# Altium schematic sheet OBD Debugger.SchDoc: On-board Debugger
size A3; CompanyName: Hitex GmbH; Address1: Greschbachstr. 12; Address2: 76229 Karlsruhe, Germany; Address3: www.hitex.com; DocumentNumber: 5; SheetNumber: 5; SheetTotal: 8; PageSetup: Record=PageOptions¦CenterHorizontal=True¦CenterVertical=True¦PrintScale=1.04¦XCorrection=1.00¦YCorrection=1.00¦PrintKind=0¦BorderSize=5000000¦LeftOffset=0¦BottomOffset=0¦Orientation=2¦PaperLength=1000¦PaperWidth=1000¦Scale=100¦PaperSource=7¦PrintQuality=1200¦MediaType=1¦DitherType=10¦PaperKind=A3¦PrintScaleMode=1
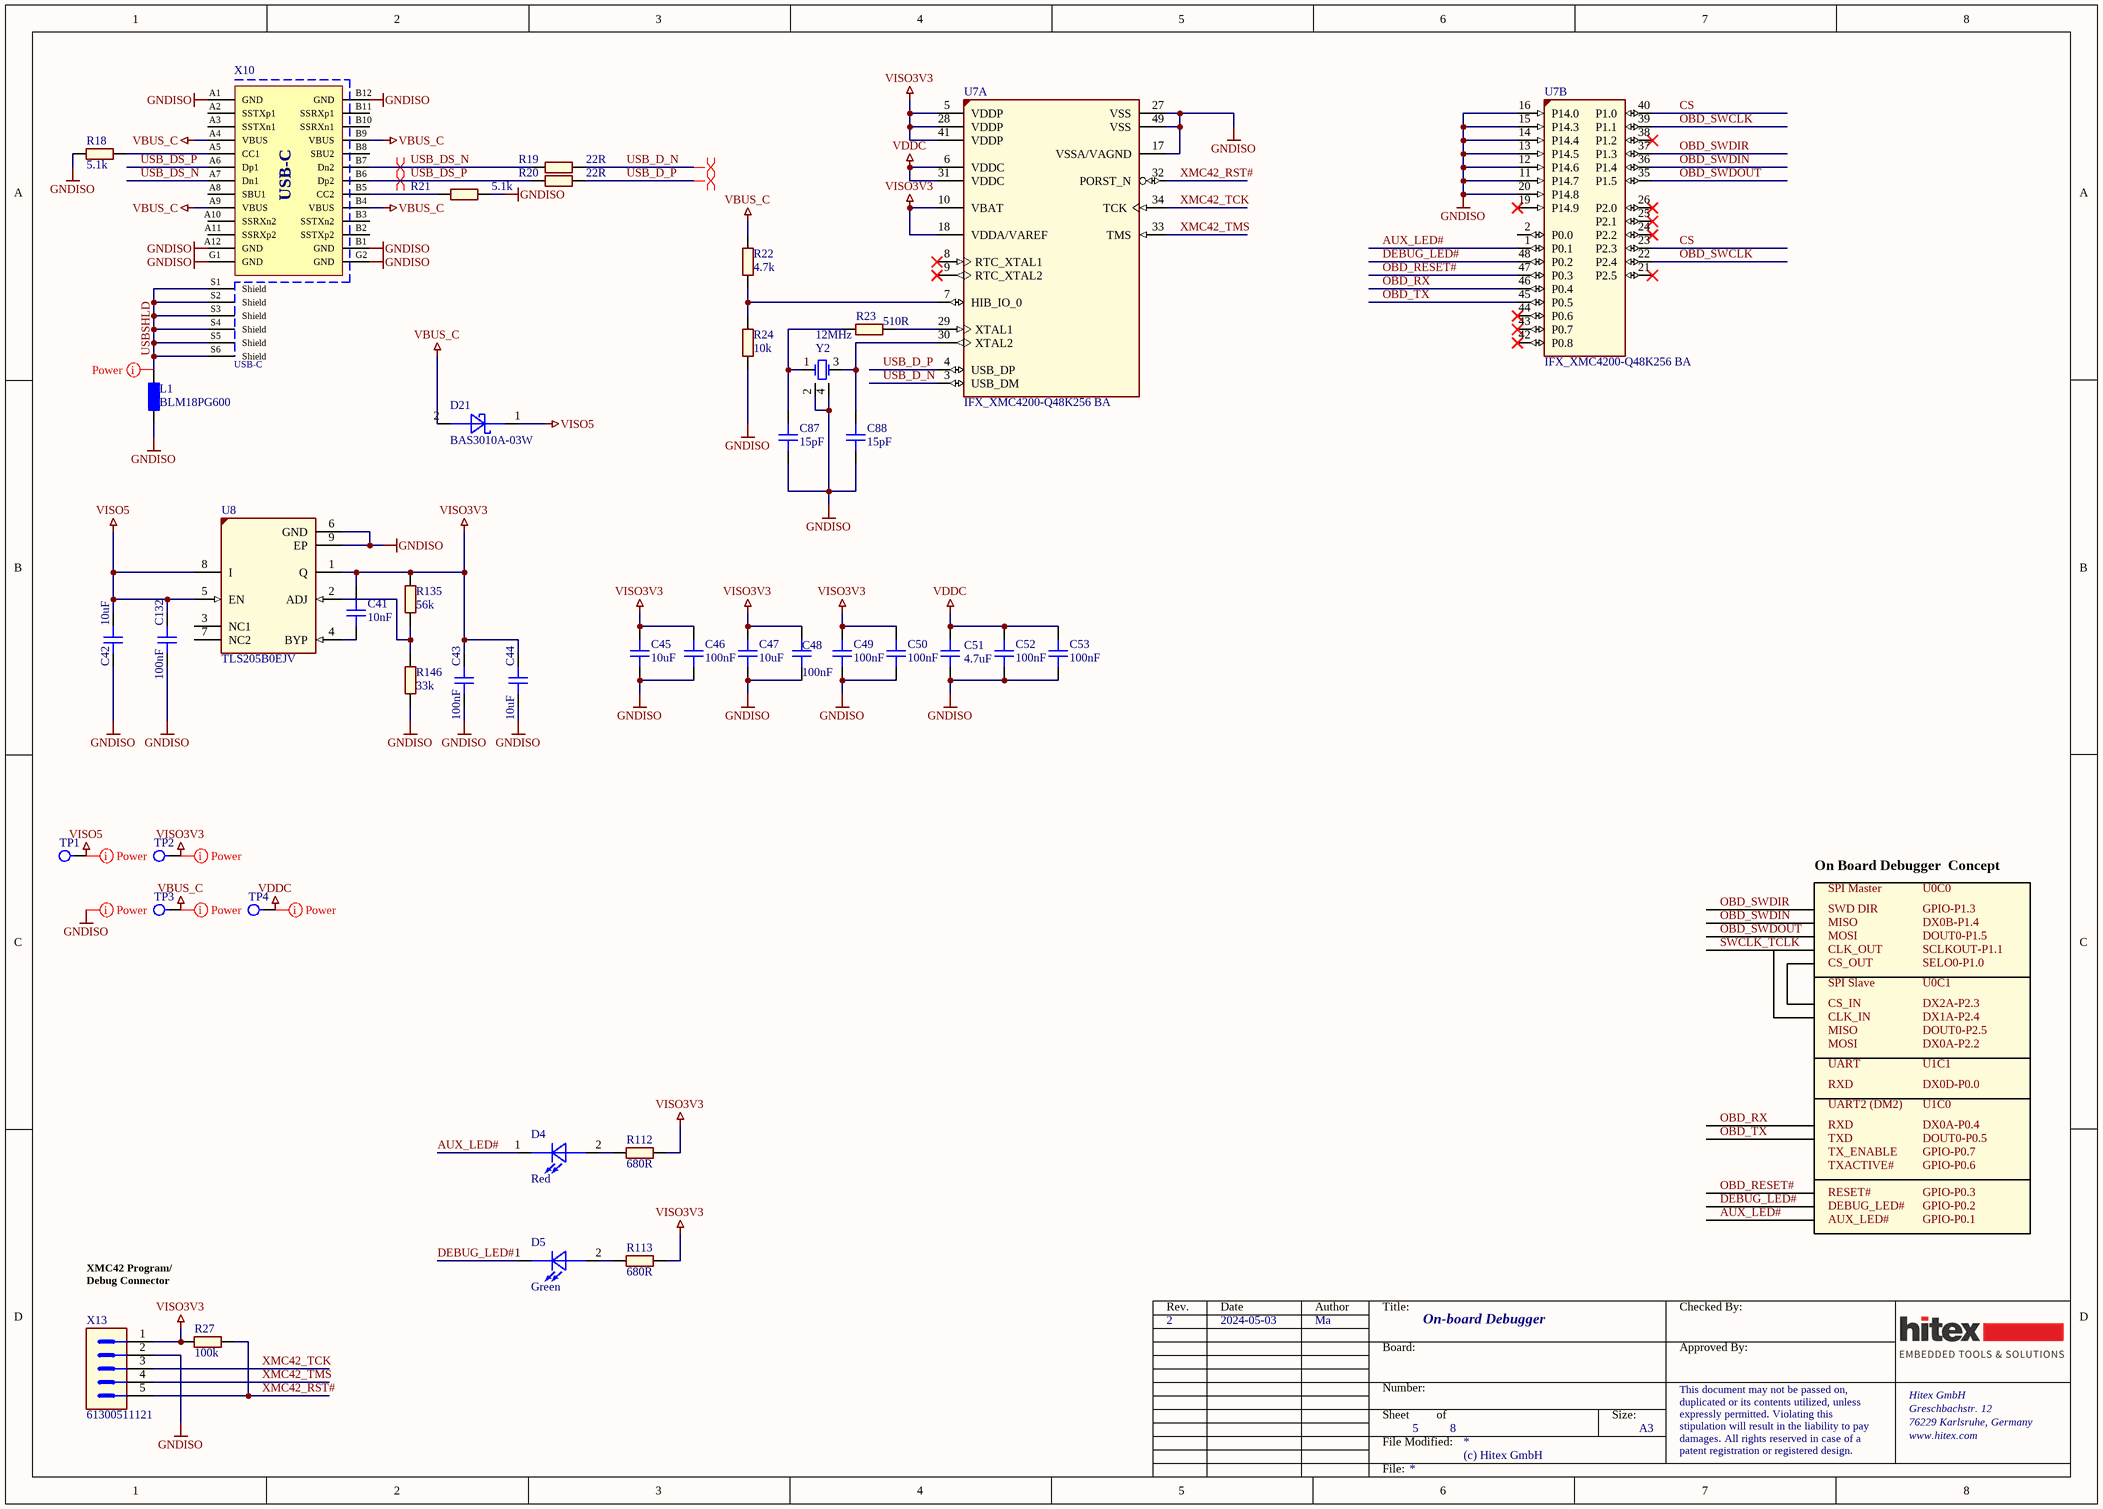
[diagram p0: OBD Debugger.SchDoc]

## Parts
C41  10nF  [CAPC1005X55N-0]
C42  10uF  [CAPC3216X180N]
C43  100nF  [CAPC1005X60N]
C44  10uF  [CAPC3216X180N]
C45  10uF  [CAPC3216X180N]
C46  100nF  [CAPC1005X55N-0]
C47  10uF  [CAPC3216X180N]
C48  100nF  [CAPC1005X55N-0]
C49  100nF  [CAPC1005X55N-0]
C50  100nF  [CAPC1005X55N-0]
C51  4.7uF  [CAPC2013X145N-3]
C52  100nF  [CAPC1005X55N-0]
C53  100nF  [CAPC1005X55N-0]
C87  15pF  [CAPC1005X55N-0]
C88  15pF  [CAPC1005X55N-0]
C132  100nF  [CAPC1005X60N]
D4  Red  [LEDSC160X80X80-2N]
D5  Green  [LEDSC160X80X40-2N]
D21  BAS3010A-03W  [SOD2513X110N]
L1  BLM18PG600  [INDC1608N]
R18  5.1k  [RESC1609X50N]
R19  22R  [RESC1005X40N]
R20  22R  [RESC1005X40N]
R21  5.1k  [RESC1609X50N]
R22  4.7k  [RESC1005X40N-1]
R23  510R  [RESC1005X40N]
R24  10k  [RESC1005X40N]
R27  100k  [RESC1005X40N]
R112  680R  [RESC1608X55N-1]
R113  680R  [RESC1608X55N-1]
R135  56k  [RESC1005X40N]
R146  33k  [RESC1005X40N]
TP1  (no value)  [TP_RD_SMD_1MM]  (no BOM)
TP2  (no value)  [TP_RD_SMD_1MM]  (no BOM)
TP3  (no value)  [TP_RD_SMD_1MM]  (no BOM)
TP4  (no value)  [TP_RD_SMD_1MM]  (no BOM)
U7  IFX_XMC4200-Q48K256 BA  [QFN50P700X700X90-49N-8]  (parts A,B of 2)
U8  TLS205B0EJV  [SOIC127P600X170-9N-3-V1]
X10  USB-C  [632723300011]
X13  61300511121  [CON-M-THT-61300511121]
Y2  12MHz  [Oscillator_3225]

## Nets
GNDISO: C42.1 C43.1 C44.1 C45.1 C46.1 C47.1 C48.1 C49.1 C50.1 C51.1 C52.1 C53.1 C87.1 C88.1 C132.1 L1.1 R18.1 R21.2 R24.1 R146.1 U7.11(P14.7) U7.12(P14.6) U7.13(P14.5) U7.14(P14.4) U7.15(P14.3) U7.16(P14.0) U7.17(VSSA/VAGND) U7.20(P14.8) U7.27(VSS) U7.49(VSS) U8.6(GND) U8.9(EP) X10.A1(GND) X10.A12(GND) X10.B1(GND) X10.B12(GND) X10.G1(GND) X10.G2(GND) X13.2 Y2.2(GND) Y2.4(GND)
VBUS_C: D21.2(Anode) R22.2 TP3.1 X10.A4(VBUS) X10.A9(VBUS) X10.B4(VBUS) X10.B9(VBUS)
VDDC: C51.2 C52.2 C53.2 TP4.1 U7.6(VDDC) U7.31(VDDC)
VISO3V3: C41.2 C43.2 C44.2 C45.2 C46.2 C47.2 C48.2 C49.2 C50.2 R27.2 R112.1 R113.2 R135.2 TP2.1 U7.5(VDDP) U7.10(VBAT) U7.18(VDDA/VAREF) U7.28(VDDP) U7.41(VDDP) U8.1(Q) X13.1
VISO5: C42.2 C132.2 D21.1(Cathode) TP1.1 U8.5(EN) U8.8(I)
AUX_LED#: D4.1(Cathode) U7.1(P0.1)
CS: U7.23(P2.3) U7.40(P1.0)
DEBUG_LED#: D5.1(Cathode) U7.48(P0.2)
OBD_RESET#: U7.47(P0.3)
OBD_RX: U7.46(P0.4)
OBD_SWCLK: U7.22(P2.4) U7.39(P1.1)
OBD_SWDIN: U7.36(P1.4)
OBD_SWDIR: U7.37(P1.3)
OBD_SWDOUT: U7.35(P1.5)
OBD_TX: U7.45(P0.5)
USB_D_N: R19.2 U7.3(USB_DM)
USB_D_P: R20.2 U7.4(USB_DP)
USB_DS_N: R19.1 X10.A7(Dn1) X10.B7(Dn2)
USB_DS_P: R20.1 X10.A6(Dp1) X10.B6(Dp2)
USBSHLD: L1.2 X10.S1(Shield) X10.S2(Shield) X10.S3(Shield) X10.S4(Shield) X10.S5(Shield) X10.S6(Shield)
XMC42_RST#: R27.1 U7.32(PORST_N) X13.5
XMC42_TCK: U7.34(TCK) X13.3
XMC42_TMS: U7.33(TMS) X13.4
NetC41_1: C41.1 U8.4(BYP)
NetC87_2: C87.2 R23.1 Y2.1(OSC1)
NetC88_2: C88.2 U7.30(XTAL2) Y2.3(OSC2)
NetD4_2: D4.2(Anode) R112.2
NetD5_2: D5.2(Anode) R113.1
NetR18_2: R18.2 X10.A5(CC1)
NetR21_1: R21.1 X10.B5(CC2)
NetR22_1: R22.1 R24.2 U7.7(HIB_IO_0)
NetR23_2: R23.2 U7.29(XTAL1)
NetR135_1: R135.1 R146.2 U8.2(ADJ)

Not connected (* = marked no-connect by the designer): U7 2(P0.0) 8(RTC_XTAL1)* 9(RTC_XTAL2)* 19(P14.9)* 21(P2.5)* 24(P2.2)* 25(P2.1)* 26(P2.0)* 38(P1.2)* 42(P0.8)* 43(P0.7)* 44(P0.6)*; U8 3(NC1) 7(NC2); X10 A2(SSTXp1) A3(SSTXn1) A8(SBU1) A10(SSRXn2) A11(SSRXp2) B2(SSTXp2) B3(SSTXn2) B8(SBU2) B10(SSRXn1) B11(SSRXp1)

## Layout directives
differential pair; differential pair class DIFF90R: USB_D_N, USB_D_P, USB_DS_N, USB_DS_P
net class Power: GNDISO, USBSHLD, VBUS_C, VDDC, VISO3V3, VISO5

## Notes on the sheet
- OBD_SWDIN
- OBD_SWDIR
- On Board Debugger  Concept
- SPI Master
- SWD DIR
- U0C0
- GPIO-P1.3
- SWCLK_TCLK
- OBD_SWDOUT
- SPI Slave
- MOSI
- CLK_OUT
- MISO
- CS_OUT
- SCLKOUT-P1.1
- DX0B-P1.4
- U0C1
- DOUT0-P1.5
- SELO0-P1.0
- CS_IN
- CLK_IN
- DX2A-P2.3
- DX1A-P2.4
- DOUT0-P2.5
- DX0A-P2.2
- OBD_RX
- UART2 (DM2)
- RXD
- UART
- DX0A-P0.4
- U1C0
- DX0D-P0.0
- U1C1
- OBD_TX
- OBD_RESET#
- TXD
- TXACTIVE#
- TX_ENABLE
- DOUT0-P0.5
- GPIO-P0.6
- GPIO-P0.7
- DEBUG_LED#
- AUX_LED#
- RESET#
- GPIO-P0.3
- GPIO-P0.2
- GPIO-P0.1
- XMC42 Program/
  Debug Connector
- 2
- 2024-05-03
- Ma
- Labels drawn without touching a wire or pin: GNDISO

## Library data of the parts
C41 = 264563: CAP / CERA / 10nF / 16V / 5% / X7R (EIA) / -55°C to 125°C / 0402(1005) / SMD / -; Multiple Parts: No; Legacy PartNumber: CAP01001706; Manufacturer: MuRata; Manufacturer Order Number: GRM155R71C103JA01; Symbol Type: Capacitor; Single; Standard; 2 Pins; Alternate View: Yes; Article Number: 264563; Version Number: V01; Combined Parameters: TC:X7R (EIA);Tol.:-5%/+5%;Vdc:16V; QuickPick: 10nF / 16V / 5% / X7R (EIA) / 0402 (1005); Type: Standard; Style: Single; Package Metric: 1005; Package Imperial: 0402; ComponentStatus: Released; PLMStatus: Not Recommended For New Designs; HTX: 01.22.0592.0
C42 C44 C45 C47 = 282249: CAP / CERA / 10uF / 50V / 20% / X5R (EIA) / -55°C to 85°C / 1206(3216) / SMD / -; Multiple Parts: No; Manufacturer: MuRata; Manufacturer Order Number: GRM31CR61H106MA12L; Symbol Type: Capacitor; Single; Standard; 2 Pins; Alternate View: Yes; Article Number: 282249; Version Number: V01; Combined Parameters: TC:X5R (EIA);Tol.:-20%/+20%;Vdc:50V; QuickPick: 10uF / 50V / 20% / X5R (EIA) / 1206 (3216); Type: Standard; Style: Single; Package Metric: 3216; Package Imperial: 1206; ComponentStatus: Released; PLMStatus: Not Recommended For New Designs; HTX: 01.22.0647.0
C43 C132 = 507459: CAP / CERA / 100nF / 50V / 10% / X7R (EIA) / -55°C to 125°C / 0402(1005) / SMD / -; Multiple Parts: No; Manufacturer: TDK Corporation; Manufacturer Order Number: C1005X7R1H104K050BE; Symbol Type: Capacitor; Single; Standard; 2 Pins; Alternate View: Yes; Article Number: 507459; Version Number: V01; Combined Parameters: TC:X7R (EIA);Tol.:-10%/+10%;Vdc:50V; QuickPick: 100nF / 50V / 10% / X7R (EIA) / 0402 (1005); Type: Standard; Style: Single; Package Metric: 1005; Package Imperial: 0402; ComponentStatus: Released; PLMStatus: Active; HTX: 01.22.0596.0
C46 C48-C50 C52 C53 = 310625: CAP / CERA / 100nF / 50V / 10% / X7R (EIA) / -55°C to 125°C / 0402(1005) / SMD / -; Multiple Parts: No; Legacy PartNumber: CAP01010920; Manufacturer: MuRata; Manufacturer Order Number: GRM155R71H104KE14D; Symbol Type: Capacitor; Single; Standard; 2 Pins; Alternate View: Yes; Article Number: 310625; Version Number: V01; Combined Parameters: TC:X7R (EIA);Tol.:-10%/+10%;Vdc:50V; QuickPick: 100nF / 50V / 10% / X7R (EIA) / 0402 (1005M); Type: Standard; Style: Single; Package Metric: 1005; Package Imperial: 0402; ComponentStatus: Released; PLMStatus: Active; HTX: 01.22.0596.0
C51 = 673682: CAP / CERA / 4.7uF / 25V / 20% / X7R (EIA) / -55°C to 125°C / 0805 / SMD / -; Multiple Parts: No; Manufacturer: Yageo; Manufacturer Order Number: CC0805MKX7R8BB475; Symbol Type: Capacitor; Single; Standard; 2 Pins; Alternate View: Yes; Article Number: 673682; Version Number: V00; Combined Parameters: TC:X7R (EIA);Tol.:-20%/+20%;Vdc:25V; QuickPick: 4.7uF / 25V / 20% / X7R (EIA) / 0805; Type: Standard; Style: Single; ComponentStatus: Released; PLMStatus: Active; HTX: 01.22.0436.0
C87 C88 = 287311: CAP / CERA / 15pF / 50V / 2% / C0G (EIA) / NP0 / -55°C to 125°C / 0402(1005) / SMD / -; Multiple Parts: No; Legacy PartNumber: CAP01006535; Manufacturer: MuRata; Manufacturer Order Number: GCM1555C1H150GA16; Symbol Type: Capacitor; Single; Standard; 2 Pins; Alternate View: Yes; Article Number: 287311; Version Number: V01; Combined Parameters: TC:C0G (EIA) / NP0;Tol.:-2%/+2%;Vdc:50V; QuickPick: 15pF / 50V / 2% / C0G (EIA) / NP0 / 0402 (1005); Type: Standard; Style: Single; Automotive Qualified: AEC Q200; Package Metric: 1005; Package Imperial: 0402; ComponentStatus: Released; PLMStatus: Active; HTX: 01.22.0669.0
D4 = 494911: ChipLED 0603, Red, 633nm, Temp Raneg(-30 to 85°C); Manufacturer: OSRAM Opto Semiconductors; Manufacturer Order Number: LSQ971-Z; Symbol Type: Standard LED Symbol, 1 Cathode, 2 Anode; Article Number: 494911; Version Number: V01; Combined Parameters: Vf:2.5V;If:25mA;Ur:12V;Ir:10uA;Pmax:-; QuickPick: LED / 603; Type: LED; Style: Single; Automotive Qualified: No; ComponentStatus: Released; PLMStatus: Active; Second Source allowed: Yes; Voltage DC (max): na; HTX: 00.96.0114.0
D5 = 678273: Chip LED, 573nm, Green, Electronic Equipment Applications; Manufacturer: OSRAM Opto Semiconductors; Manufacturer Order Number: LG Q396-PS-35; Symbol Type: Standard LED Symbol, 1 Cathode, 2 Anode; Article Number: 678273; Version Number: V00; Combined Parameters: Vf:2.4V;If:30mA;Ur:12V;Ir:10uA;Pmax:-; QuickPick: LED / 0603; Style: Single; Automotive Qualified: No; ComponentStatus: Released; PLMStatus: Active; Second Source allowed: Yes; Voltage DC (max): na; HTX: 00.96.0122.0
D21 = 420617: Medium Power AF Schottky Diode; Legacy PartNumber: IFX01400145; Manufacturer: Infineon Technologies; Symbol Type: Standard Schottky Diode Symbol, 1 Cathode, 2 Anode; Article Number: 420617; Version Number: V01; Combined Parameters: Vf:410mV;If:1A;Ur:30V;Ir:200uA;Pmax:-; QuickPick: Schottky Diode / SOD323; Style: Single; Automotive Qualified: AEC Q101; ComponentStatus: Released; PLMStatus: Active; Second Source allowed: Yes; Voltage DC (max): na; HTX: 01.41.0047.0
L1 = BLM18PG600SN1D: FERRITE, SMD, 60 OHM, 0603; PartNumber: 01.30.0224.0; Manufacturer: Murata; Designer: Ma; CheckOrientation: false
R18 R21 = 346002: RES / STD / 5.1k / 100mW / 1% / 100ppm/K / -55°C to 155°C / 0603(1608) / SMD / -; Multiple Parts: No; Legacy PartNumber: RES01801223; Manufacturer: Vishay; Manufacturer Order Number: CRCW06035K10FK; Symbol Type: Resistor; Single; Standard; 2 Pins; Alternate View: Yes; Article Number: 346002; Version Number: V01; Combined Parameters: TCR:100ppm/K;Tol.:-1%/+1%;Vdc:75V;Idc:-;P:100mW; QuickPick: 5.1k / 1% / 0.1 / 0603 (1608); Style: Single; Automotive Qualified: AEC Q200; Package Metric: 1608; Package Imperial: 0603; ComponentStatus: Released; PLMStatus: Active; Voltage DC (max): 75V; HTX: 01.02.0481.0
R19 R20 = 340637: RES / STD / 22R / 63mW / 1% / 100ppm/K / -55°C to 155°C / 0402 / SMD / -; Multiple Parts: No; Legacy PartNumber: RES01800151; Manufacturer: Vishay; Manufacturer Order Number: CRCW040222R0FK; Symbol Type: Resistor; Single; Standard; 2 Pins; Alternate View: Yes; Article Number: 340637; Version Number: V01; Combined Parameters: TCR:100ppm/K;Tol.:-1%/+1%;Vdc:50V;Idc:-;P:63mW; QuickPick: 22R / 1% / 0.063 / 0402; Style: Single; Automotive Qualified: AEC Q200; ComponentStatus: Released; PLMStatus: Active; Voltage DC (max): 50V; HTX: 01.02.0779.0
R22 = 327541: RES / STD / 4.7k / 63mW / 1% / 100ppm/K / -55°C to 155°C / 0402(1005) / SMD / -; Multiple Parts: No; Manufacturer: Yageo; Manufacturer Order Number: RC0402FR-074K7L; Symbol Type: Resistor; Single; Standard; 2 Pins; Alternate View: Yes; Article Number: 327541; Version Number: V01; Combined Parameters: TCR:100ppm/K;Tol.:-1%/+1%;Vdc:50V;Idc:-;P:63mW; QuickPick: 4.7k / 1% / 0.063 / 0402 (1005); Style: Single; Package Metric: 1005; Package Imperial: 0402; ComponentStatus: Released; PLMStatus: Active; Voltage DC (max): 50V; HTX: 01.02.0737.0
R23 = 341427: RES / STD / 510R / 63mW / 1% / 100ppm/K / -55°C to 155°C / 0402(1005) / SMD / -; Multiple Parts: No; Legacy PartNumber: RES01800309; Manufacturer: Vishay; Manufacturer Order Number: CRCW0402510RFK; Symbol Type: Resistor; Single; Standard; 2 Pins; Alternate View: Yes; Article Number: 341427; Version Number: V01; Combined Parameters: TCR:100ppm/K;Tol.:-1%/+1%;Vdc:50V;Idc:-;P:63mW; QuickPick: 510R / 1% / 0.063 / 0402 (1005); Style: Single; Automotive Qualified: AEC Q200; Package Metric: 1005; Package Imperial: 0402; ComponentStatus: Released; PLMStatus: Active; Voltage DC (max): 50V; HTX: 01.02.2011.0
R24 = 342167: RES / STD / 10k / 63mW / 1% / 100ppm/K / -55°C to 155°C / 0402(1005) / SMD / -; Multiple Parts: No; Legacy PartNumber: RES01800457; Manufacturer: Vishay; Manufacturer Order Number: CRCW040210K0FK; Symbol Type: Resistor; Single; Standard; 2 Pins; Alternate View: Yes; Article Number: 342167; Version Number: V01; Combined Parameters: TCR:100ppm/K;Tol.:-1%/+1%;Vdc:50V;Idc:-;P:63mW; QuickPick: 10k / 1% / 0.063 / 0402 (1005); Style: Single; Automotive Qualified: AEC Q200; Package Metric: 1005; Package Imperial: 0402; ComponentStatus: Released; PLMStatus: Active; Voltage DC (max): 50V; HTX: 01.02.0703.0
R27 = 342737: RES / STD / 100k / 63mW / 1% / 100ppm/K / -55°C to 155°C / 0402 / SMD / -; Multiple Parts: No; Legacy PartNumber: RES01800571; Manufacturer: Vishay; Manufacturer Order Number: CRCW0402100KFK; Symbol Type: Resistor; Single; Standard; 2 Pins; Alternate View: Yes; Article Number: 342737; Version Number: V01; Combined Parameters: TCR:100ppm/K;Tol.:-1%/+1%;Vdc:50V;Idc:-;P:63mW; QuickPick: 100k / 1% / 0.063 / 0402; Style: Single; Automotive Qualified: AEC Q200; ComponentStatus: Released; PLMStatus: Active; Voltage DC (max): 50V; HTX: 01.02.0716.0
R112 R113 = 330423: RES / STD / 680R / 100mW / 1% / 100ppm/K / -55°C to 155°C / 0603(1608) / SMD / -; Multiple Parts: No; Manufacturer: Yageo; Manufacturer Order Number: AC0603FR-07680RL; Symbol Type: Resistor; Single; Standard; 2 Pins; Alternate View: Yes; Article Number: 330423; Version Number: V01; Combined Parameters: TCR:100ppm/K;Tol.:-1%/+1%;Vdc:75V;Idc:-;P:100mW; QuickPick: 680R / 1% / 0.1 / 0603 (1608); Style: Single; Automotive Qualified: AEC Q200; Package Metric: 1608; Package Imperial: 0603; ComponentStatus: Released; PLMStatus: Active; Voltage DC (max): 75V; HTX: 01.02.0464.0
R135 = 342592: RES / STD / 56k / 63mW / 1% / 100ppm/K / -55°C to 155°C / 0402(1005) / SMD / -; Multiple Parts: No; Legacy PartNumber: RES01800542; Manufacturer: Vishay; Manufacturer Order Number: CRCW040256K0FK; Symbol Type: Resistor; Single; Standard; 2 Pins; Alternate View: Yes; Article Number: 342592; Version Number: V01; Combined Parameters: TCR:100ppm/K;Tol.:-1%/+1%;Vdc:50V;Idc:-;P:63mW; QuickPick: 56k / 1% / 0.063 / 0402 (1005); Style: Single; Automotive Qualified: AEC Q200; Package Metric: 1005; Package Imperial: 0402; ComponentStatus: Released; PLMStatus: Active; Voltage DC (max): 50V; HTX: 01.02.0770.0
R146 = 342452: RES / STD / 33k / 63mW / 1% / 100ppm/K / -55°C to 155°C / 0402(1005) / SMD / -; Multiple Parts: No; Legacy PartNumber: RES01800514; Manufacturer: Vishay; Manufacturer Order Number: CRCW040233K0FK; Symbol Type: Resistor; Single; Standard; 2 Pins; Alternate View: Yes; Article Number: 342452; Version Number: V01; Combined Parameters: TCR:100ppm/K;Tol.:-1%/+1%;Vdc:50V;Idc:-;P:63mW; QuickPick: 33k / 1% / 0.063 / 0402 (1005); Style: Single; Automotive Qualified: AEC Q200; Package Metric: 1005; Package Imperial: 0402; ComponentStatus: Released; PLMStatus: Active; Voltage DC (max): 50V; HTX: 01.02.0765.0
TP1-TP4 = Testpad_Round: Testpad SMD / THT; PartNumber: -NoPartNumber-; Designer: Ma; CheckOrientation: false
U7 = 419942: Microcontroller Series for Industrial Applications; Multiple Parts: Yes; Manufacturer: Infineon Technologies; Symbol Type: Microcontroller Series with ARM Cortex-M4 processor core for Industrial Applications; Alternate View: No; Article Number: 419942; Version Number: V01; Combined Parameters: App.:Industrial;-;Vdc min/max:3.13V/3.63V;Fmax:80MHz;RAM:40KB;ROM:16KB;Flash:256KB; QuickPick: 3.63V - 3.13V / PG-VQFN-48-71; ComponentStatus: Released; PLMStatus: Active; Voltage DC (max): na; HTX: 00.80.0580.0
U8 = 592428: Micropower, low noise, low dropout voltage regulator, Designed for use in battery-powered systems, the low quiescent current of 30 µA makes it an ideal choice; Multiple Parts: No; Manufacturer: Infineon Technologies; Symbol Type: Low Dropout, Low Noise, Linear Voltage Post Regulator, 3.3V, 500 mA; Article Number: 592428; Version Number: V01; Legacy DeviceID: IFX_TLS205B0EJV; Combined Parameters: Linear - -;Vo:1.19V to 1.25V; QuickPick: Linear / PG-DSO-8-52; Automotive Qualified: Yes; ComponentStatus: Released; PLMStatus: Active; Voltage DC (max): na; HTX: 00.40.0359.0
X10 = 632723300011: USB 3.1 Type C, Receptacle, Horizontal, THR/SMT, 24 Pin, 5A, 20V, -40 to +105degC; Manufacturer: Wurth Elektronik; PartNumber: 03.16.0206.0; Designer: Ma; CheckOrientation: false
X13 = 654247: WR-PHD 2.54 mm Pitch, 5Pins, THT Pin Header; Manufacturer: Wurth Elektronik; Article Number: 654247; Version Number: V00; Legacy DeviceID: WE_61300511121; Combined Parameters: Board-to-Board/Cable Header (male);5x1;Mounting:THT;Orient:0° (vertical);Shielded:No; QuickPick: 0° (vertical) / Board-to-Board/Cable; Style: Strip; Automotive Qualified: No; ComponentStatus: Released; PLMStatus: Active; Second Source allowed: Yes; Voltage DC (max): na; HTX: 03.20.0004.0
Y2 = 12MHz/3225/4PAD: 12MHz 8pF 50ppm/15ppm; PartNumber: 00.98.0092.0; Manufacturer: NDK; Designer: Ar; Value: NX3225SA 12MHZ AT-W; CheckOrientation: true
